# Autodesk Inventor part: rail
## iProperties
Author: Elise Moss
Created: 2001-09
Part Number: rail
Document SubType Name: Modeling
Designer: Elise Moss
Control State: 0
Master: False
Checked Out: False
PropertySet Name: Design Tracking Control
Shininess: 64.0
Angle Display Precision: 2
Document Length Units: 11272
Document Angle Units: 11286
Document Time Units: 11279
Document Mass Units: 11290
Document Length Units Precision: 3
Document Angle Units Precision: 2
Compacted: False
PropertySet Name: _Private Model Information
Density: 0.0
Volumn: 0.0
Area: 0.0
PropertySet Name: Model Information
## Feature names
1. Extrusion1
2. Hole1
